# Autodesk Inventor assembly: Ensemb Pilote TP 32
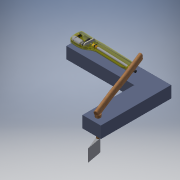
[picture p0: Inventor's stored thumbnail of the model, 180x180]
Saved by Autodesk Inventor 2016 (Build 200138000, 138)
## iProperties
Created: 2013-10
Part Number: Ensemb Pilote TP 32
Document SubType Name: Assembly
Designer: Bernard QUIVRIN
Author: Bernard QUIVRIN
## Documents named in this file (8)
- D:\Cours\En cours\inventor2012-TP32\Ensemb Pilote TP 32 Elève.iam
- D:\Cours\En cours\inventor2012-TP32\banc.ipt
- D:\Cours\En cours\inventor2012-TP32\Ensemble_Safran_Barre.iam
- D:\Cours\En cours\inventor2012-TP32\Ensemble_Corps.iam
- D:\Cours\En cours\inventor2012-TP32\Ensemble_Axe_fixation.iam
- D:\Cours\En cours\inventor2012-TP32\Ensemble_Axe_moteur.iam
- D:\Cours\En cours\inventor2012-TP32\Ensemble_Vis_d'entraînement.iam
- D:\Cours\En cours\inventor2012-TP32\Ensemble_Tige.iam
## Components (7 placed, 7 different names)
1. banc:1 — Logement:1, Affleurement:1, Plaquage:1, Angle:1
2. Ensemble_Safran_Barre:1 [sub-assembly] — Logement:1, Plaquage:12
3. Ensemble_Corps:1 [sub-assembly] — Plaquage:3, Plaquage:4, Plaquage:5, Plaquage:6, Plaquage:7, Plaquage:8, Plaquage:9
4. Ensemble_Axe_fixation:1 [sub-assembly] — Affleurement:1, Plaquage:1, Plaquage:3, Plaquage:4
5. Ensemble_Axe_moteur:1 [sub-assembly] — Plaquage:5, Plaquage:6
6. Ensemble_Vis_d'entraînement:1 [sub-assembly] — Plaquage:7, Plaquage:8, Plaquage:10, Plaquage:11
7. Ensemble_Tige:1 [sub-assembly] — Plaquage:9, Plaquage:10, Plaquage:11, Angle:1, Plaquage:12
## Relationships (14: Mate 11, Insert 1, Flush 1, Angle 1)
- Logement:1 [Insert]: banc:1 ↔ Ensemble_Safran_Barre:1
- Affleurement:1 [Flush]: banc:1 ↔ Ensemble_Axe_fixation:1
- Plaquage:1 [Mate]: banc:1 ↔ Ensemble_Axe_fixation:1
- Plaquage:3 [Mate]: Ensemble_Corps:1 ↔ Ensemble_Axe_fixation:1
- Plaquage:4 [Mate]: Ensemble_Corps:1 ↔ Ensemble_Axe_fixation:1
- Plaquage:5 [Mate]: Ensemble_Corps:1 ↔ Ensemble_Axe_moteur:1
- Plaquage:6 [Mate]: Ensemble_Corps:1 ↔ Ensemble_Axe_moteur:1
- Plaquage:7 [Mate]: Ensemble_Corps:1 ↔ Ensemble_Vis_d'entraînement:1
- Plaquage:8 [Mate]: Ensemble_Corps:1 ↔ Ensemble_Vis_d'entraînement:1
- Plaquage:9 [Mate]: Ensemble_Corps:1 ↔ Ensemble_Tige:1
- Plaquage:10 [Mate]: Ensemble_Vis_d'entraînement:1 ↔ Ensemble_Tige:1
- Plaquage:11 [Mate]: Ensemble_Vis_d'entraînement:1 ↔ Ensemble_Tige:1
- Angle:1: banc:1 ↔ Ensemble_Tige:1
- Plaquage:12 [Mate]: Ensemble_Safran_Barre:1 ↔ Ensemble_Tige:1
